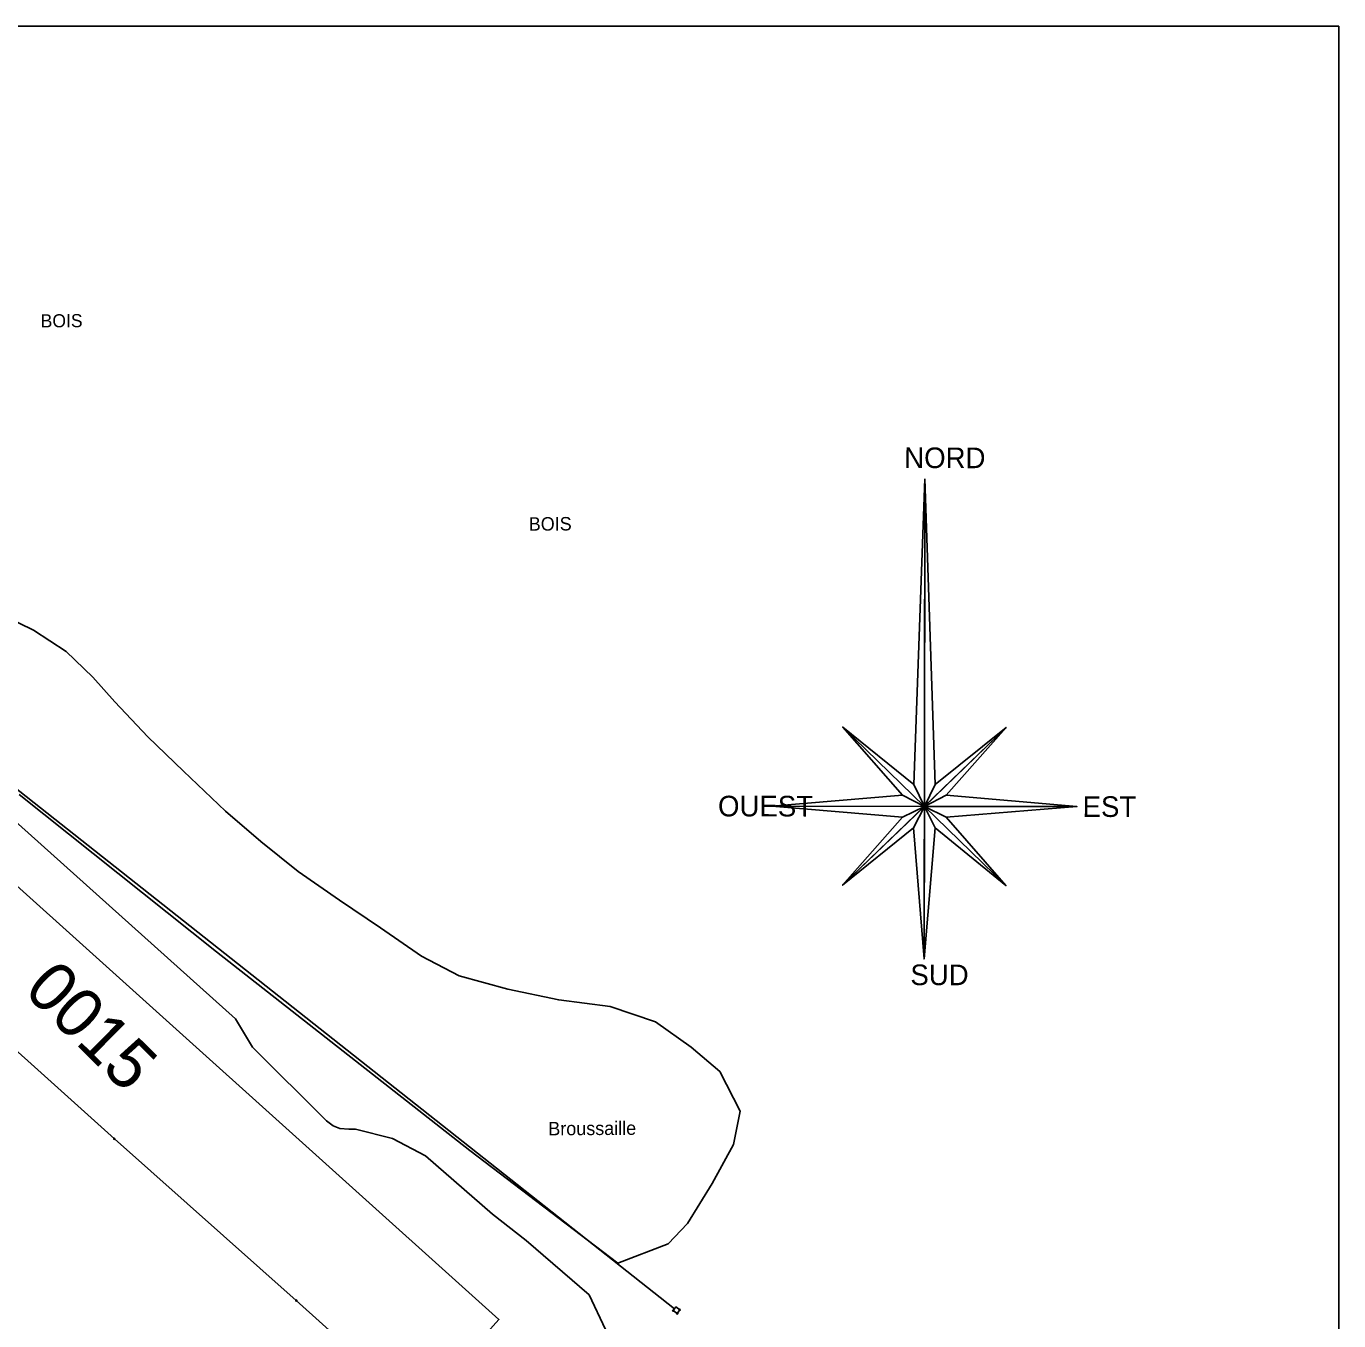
# Model space of a CAD drawing. Extents: x 344013 to 344423, y 298505 to 298795.
# Drawn here: x 344325.2 to 344422.9, y 298695.5 to 298791.9 of the extents above; entities that cross this region are included whole.
import ezdxf

# ---------------------------------------------------------------- set-up
doc = ezdxf.new("R2010")
doc.units = 0
for name, color, linetype in [('Default', 7, 'Continuous'), ('DH_CADRE -CARTOUCHE', 7, 'Continuous'), ('DH_NORD', 7, 'Continuous'), ('PS_CONST', 7, 'Continuous'), ('PS_WELD', 7, 'Continuous'), ('TOPO_COURBE NIVEAU', 7, 'Continuous'), ('TOPO_POINT', 7, 'Continuous'), ('VOIRIE_ESPACE VERT', 7, 'Continuous')]:
    doc.layers.add(name, color=color, linetype=linetype)

# ---------------------------------------------------------------- blocks, each defined once
blk = doc.blocks.new('POINT_DISPLAY')
at = {"layer": 'Default'}
blk.add_circle((0, 0), 0.05, dxfattribs=at)

msp = doc.modelspace()

# ---------------------------------------------------------------- linework, layer by layer
at = {"layer": 'DH_CADRE -CARTOUCHE'}
for points in [[(344012.906, 298504.876), (344422.906, 298504.876), (344422.906, 298791.876), (344012.906, 298791.876)], [(344300.695, 298736.911), (344309.284, 298729.159), (344318.375, 298721.074), (344331.766, 298709.041), (344345.307, 298697.002), (344354.351, 298688.866), (344356.37, 298691.11), (344358.623, 298689.083), (344360.288, 298690.966), (344358.051, 298692.978), (344360.392, 298695.581), (344306.859, 298743.741)], [(344373.856, 298696.309), (344373.662, 298696.044), (344373.374, 298696.255), (344373.568, 298696.52)]]:
    msp.add_lwpolyline(points, close=True, dxfattribs=at)
at = {"layer": 'DH_NORD'}
for p, q in [((344392.095, 298758.178), (344391.264, 298735.427)), ((344392.095, 298758.178), (344392.045, 298722.434)), ((344398.149, 298739.674), (344385.973, 298727.915)), ((344385.989, 298739.691), (344390.43, 298734.628)), ((344398.133, 298727.898), (344385.989, 298739.691)), ((344398.149, 298739.674), (344392.864, 298735.425)), ((344403.421, 298733.778), (344393.694, 298734.624)), ((344380.701, 298733.81), (344390.428, 298732.996)), ((344403.421, 298733.778), (344380.701, 298733.81)), ((344398.133, 298727.898), (344393.692, 298732.992)), ((344385.973, 298727.915), (344391.259, 298732.195)), ((344392.045, 298722.434), (344392.859, 298732.193))]:
    msp.add_line(p, q, dxfattribs=at)
for points in [[(344392.095, 298758.178), (344392.864, 298735.425), (344398.149, 298739.674), (344393.694, 298734.624), (344403.421, 298733.778), (344393.692, 298732.992), (344398.133, 298727.898), (344392.859, 298732.193), (344392.045, 298722.434), (344391.259, 298732.195), (344385.973, 298727.915), (344390.428, 298732.996), (344380.701, 298733.81), (344390.43, 298734.628), (344385.989, 298739.691), (344391.264, 298735.427)], [(344392.095, 298758.178), (344392.061, 298733.794), (344392.864, 298735.425), (344392.864, 298735.425)], [(344385.989, 298739.691), (344392.061, 298733.794), (344391.264, 298735.427), (344391.264, 298735.427)], [(344398.149, 298739.674), (344393.694, 298734.624), (344392.061, 298733.794)], [(344380.701, 298733.81), (344392.061, 298733.794), (344390.43, 298734.628), (344390.43, 298734.628)], [(344385.973, 298727.915), (344390.428, 298732.996), (344392.061, 298733.794)], [(344392.045, 298722.434), (344392.061, 298733.794), (344391.259, 298732.195), (344391.259, 298732.195)], [(344403.421, 298733.778), (344392.061, 298733.794), (344393.692, 298732.992), (344393.692, 298732.992)], [(344398.133, 298727.898), (344392.061, 298733.794), (344392.859, 298732.193), (344392.859, 298732.193)]]:
    msp.add_lwpolyline(points, close=True, dxfattribs=at)
at = {"layer": 'PS_WELD'}
msp.add_lwpolyline([(344267.039, 298730.273), (344294.784, 298758.546), (344373.471, 298696.387)], dxfattribs=at)
at = {"layer": 'TOPO_COURBE NIVEAU'}
msp.add_lwpolyline([(344369.546, 298692.262), (344367.098, 298697.415), (344362.432, 298701.465), (344359.917, 298703.421), (344354.93, 298707.779), (344352.46, 298709.058), (344349.707, 298709.77), (344349.226, 298709.748), (344348.55, 298709.812), (344348.063, 298710.017), (344347.551, 298710.387), (344342.046, 298715.864), (344340.783, 298717.982), (344294.711, 298759.292)], dxfattribs=at)
at = {"layer": 'VOIRIE_ESPACE VERT'}
msp.add_lwpolyline([(344321.545, 298748.944), (344325.748, 298746.901), (344328.178, 298745.33), (344330.156, 298743.409), (344331.813, 298741.573), (344334.247, 298738.974), (344336.903, 298736.421), (344340.027, 298733.428), (344342.667, 298731.173), (344345.441, 298728.941), (344348.529, 298726.82), (344351.589, 298724.744), (344354.623, 298722.63), (344357.43, 298721.17), (344361.056, 298720.181), (344364.839, 298719.38), (344368.664, 298718.901), (344372.045, 298717.762), (344374.699, 298715.872), (344376.83, 298714.05), (344378.359, 298711.098), (344377.851, 298708.63), (344376.273, 298705.705), (344374.435, 298702.727), (344372.985, 298701.22), (344369.234, 298699.792), (344358.236, 298708.16), (344339.365, 298722.962), (344324.681, 298734.684)], dxfattribs=at)

# ---------------------------------------------------------------- block references
at = {"layer": 'TOPO_POINT'}
for p in [(344331.766, 298709.041), (344345.307, 298697.002), (344373.374, 298696.255), (344373.662, 298696.044), (344373.856, 298696.309)]:
    msp.add_blockref('POINT_DISPLAY', p, dxfattribs=at)

# ---------------------------------------------------------------- texts
at = {"layer": 'DH_NORD'}
for s, p in [('NORD', (344390.56, 298758.98)), ('OUEST', (344376.7, 298733.048)), ('EST', (344403.836, 298733.01)), ('SUD', (344391.019, 298720.484))]:
    msp.add_text(s, height=1.536, rotation=359.91987, dxfattribs=at).set_placement(p)
at = {"layer": 'PS_CONST'}
for s, height, rotation, p in [('BOIS', 0.9758, 0.36645, (344326.285, 298769.453)), ('BOIS', 1.0003, 0.36644, (344362.615, 298754.318)), ('0015', 3.662, 315.36646, (344324.92, 298719.994)), ('Broussaille', 1.00027, 0.36645, (344364.069, 298709.297))]:
    msp.add_text(s, height=height, rotation=rotation, dxfattribs=at).set_placement(p)

doc.saveas('drawing.dxf')
